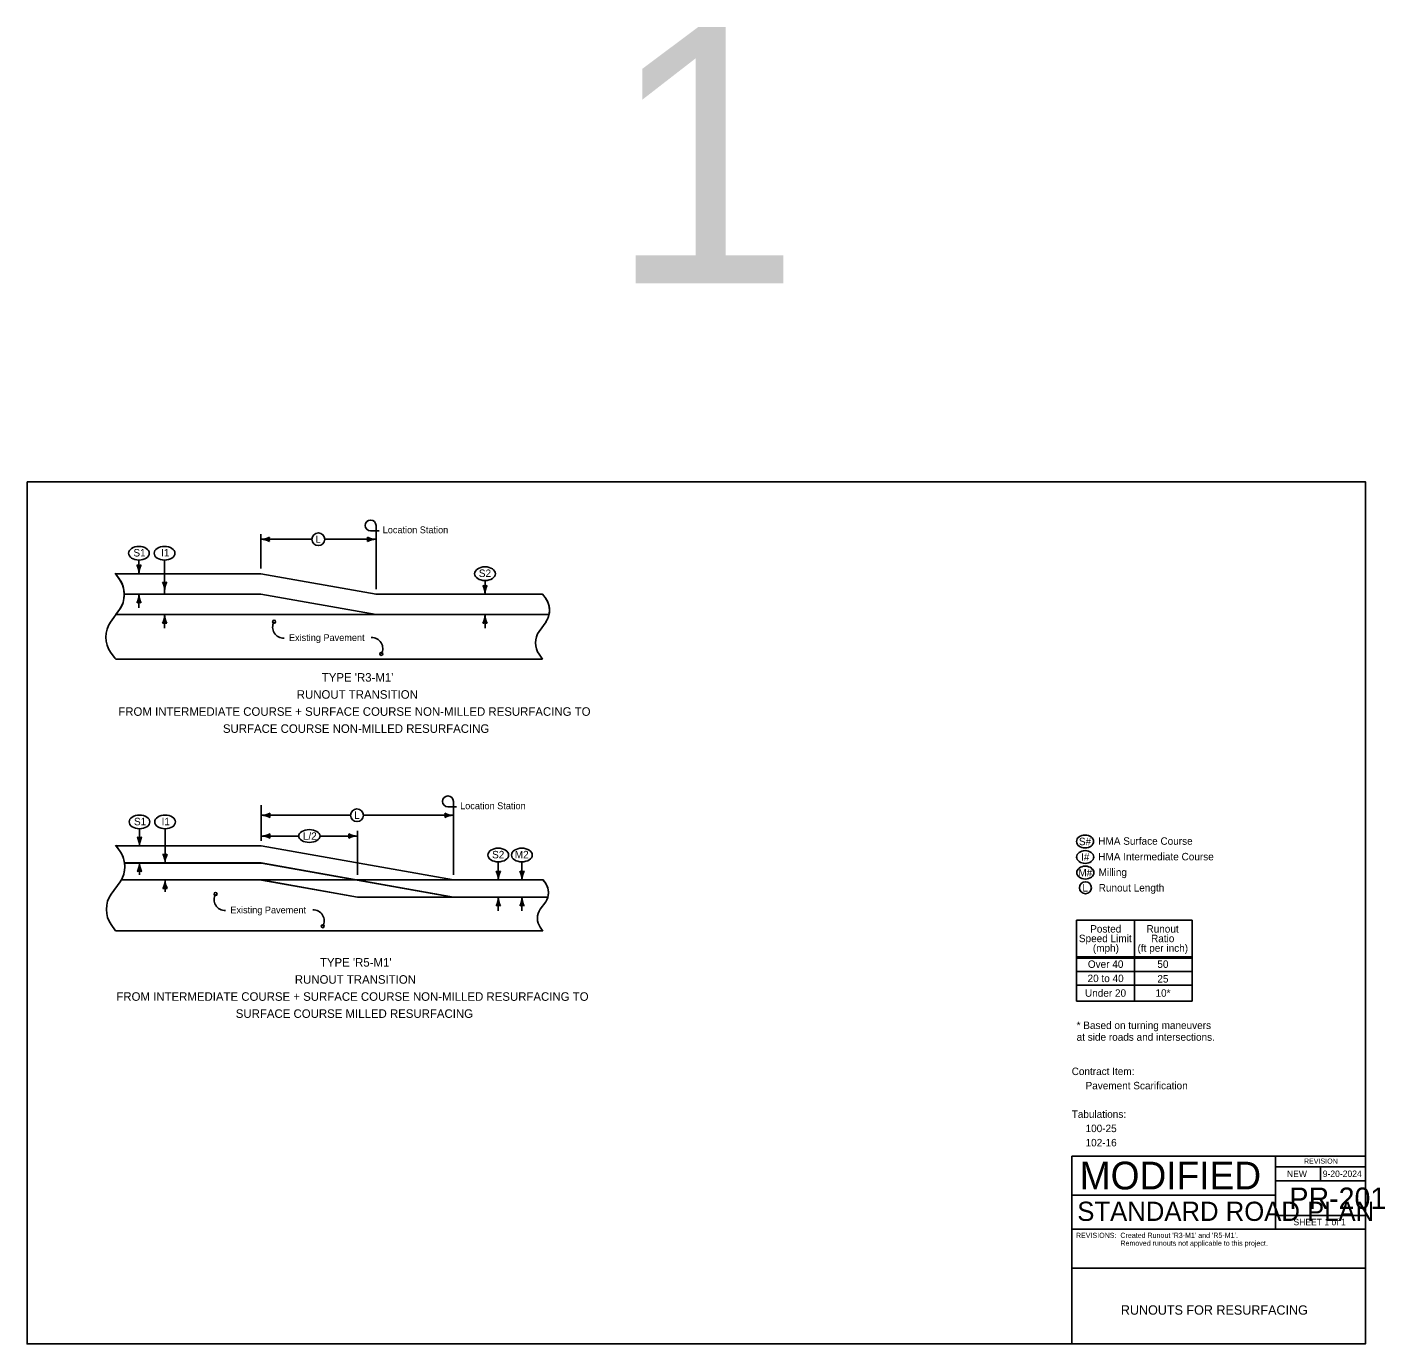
# Model space of a CAD drawing. Extents: x 10133 to 81668, y 2218 to 11018.
# Drawn here: x 10133 to 13313, y 7924 to 11009 of the extents above; entities that cross this region are included whole.
import ezdxf

# ---------------------------------------------------------------- set-up
doc = ezdxf.new("R2010")
doc.units = 0
for name, color, linetype in [('Default', 7, 'Continuous'), ('dsnNonPlotable', 7, 'Continuous'), ('dsnShtPlotShapeBatchPrint', 7, 'Continuous'), ('dsnStdBlock', 7, 'Continuous'), ('dsnStdBlockModified', 7, 'Continuous'), ('dsnStdBlockNotModified', 7, 'Continuous'), ('dsnStdBorder', 7, 'Continuous'), ('SheetBorder', 7, 'Continuous'), ('SheetText', 7, 'Continuous')]:
    doc.layers.add(name, color=color, linetype=linetype)

msp = doc.modelspace()

# ---------------------------------------------------------------- linework, layer by layer
at = {"layer": 'Default'}
for points in [[(10349.3, 9715.2), (10339.4, 9728.6), (10679.8, 9728.6), (10949.8, 9680.6), (11339.8, 9680.6), (11348, 9669.5)], [(11355.1, 9632.6), (10949.8, 9632.6), (10679.8, 9680.6), (10360, 9680.6)], [(10350.5, 9077.5), (10340.7, 9090.9), (10681.1, 9090.9), (11131.1, 9010.9), (11341.1, 9010.9), (11347.3, 9002.4)], [(11352.4, 8970.9), (11129.6, 8970.9), (10681.3, 9050.6), (10360.7, 9050.6)]]:
    msp.add_lwpolyline(points, dxfattribs=at)
for centre, major_axis, ratio, start_param in [((10323.3, 9679.9), (0, -50), 0.732645, 1.585583), ((11328.3, 9642.6), (0, -38), 0.732598, 1.304509), ((10324.6, 9042.1), (0, -50), 0.732645, 1.74011), ((11331.8, 8981.2), (0, -30), 0.73263, 1.219806)]:
    msp.add_ellipse(centre, major_axis=major_axis, ratio=ratio, start_param=start_param, end_param=2.356194, dxfattribs=at)
at = {"layer": 'dsnNonPlotable'}
for points in [[(10360, 9680.6), (10679.8, 9680.6), (10949.8, 9632.6), (10340.5, 9632.6), (10349.2, 9644.5)], [(10360.7, 9050.6), (10681.3, 9050.6), (11129.6, 8970.9), (10906.1, 8970.9), (10681.3, 9010.6), (10353.2, 9010.9)]]:
    msp.add_lwpolyline(points, dxfattribs=at)
for centre, start_param, end_param in [((10323.3, 9679.9), 0.785304, 1.585583), ((10324.6, 9042.1), 0.89539, 1.74011)]:
    msp.add_ellipse(centre, major_axis=(0, -50), ratio=0.732645, start_param=start_param, end_param=end_param, dxfattribs=at)
at = {"layer": 'dsnStdBlock'}
for p, q in [((10937.1, 9828.9), (10957.4, 9828.9)), ((10949.8, 9821.3), (10949.8, 9841.6)), ((10679.8, 9821.3), (10679.8, 9740.6)), ((10679.8, 9809.3), (10799.8, 9809.3)), ((10829.8, 9809.3), (10949.8, 9809.3)), ((10949.8, 9821.3), (10949.8, 9692.6)), ((10394.4, 9760.6), (10394.4, 9728.6)), ((10394.4, 9760.6), (10394.4, 9728.6)), ((10454.4, 9760.6), (10454.4, 9680.6)), ((10454.4, 9760.6), (10454.4, 9680.6)), ((10338.5, 9729.9), (10349.2, 9715.2)), ((10338.5, 9729.9), (10349.2, 9715.2)), ((10339.8, 9728.6), (10679.8, 9728.6)), ((10339.8, 9728.6), (10679.8, 9728.6)), ((10949.8, 9680.6), (10679.8, 9728.6)), ((11205.1, 9712.6), (11205.1, 9680.6)), ((11205.1, 9712.6), (11205.1, 9680.6)), ((10359.4, 9680.6), (10679.8, 9680.6)), ((10359.4, 9680.6), (10679.8, 9680.6)), ((10394.4, 9680.6), (10394.4, 9648.6)), ((10394.4, 9680.6), (10394.4, 9648.6)), ((10949.8, 9632.6), (10679.8, 9680.6)), ((10949.8, 9680.6), (11339.8, 9680.6)), ((10949.8, 9680.6), (11339.8, 9680.6)), ((11339.8, 9680.6), (11348, 9669.5)), ((11339.8, 9680.6), (11348, 9669.5)), ((10349.2, 9644.5), (10327.8, 9615.2)), ((10349.2, 9644.5), (10327.8, 9615.2)), ((10340.5, 9632.6), (10949.8, 9632.6)), ((10340.5, 9632.6), (10949.8, 9632.6)), ((10454.4, 9632.6), (10454.4, 9600.6)), ((10454.4, 9632.6), (10454.4, 9600.6)), ((10949.8, 9632.6), (11355.1, 9632.6)), ((10949.8, 9632.6), (11355.1, 9632.6)), ((11129.8, 9632.6), (11339.8, 9632.6)), ((11129.8, 9632.6), (11339.8, 9632.6)), ((11205.1, 9632.6), (11205.1, 9600.6)), ((11205.1, 9632.6), (11205.1, 9600.6)), ((11348, 9615.8), (11331.7, 9593.5)), ((11348, 9615.8), (11331.7, 9593.5)), ((10327.8, 9544.5), (10338.5, 9529.9)), ((10327.8, 9544.5), (10338.5, 9529.9)), ((10339.8, 9528.6), (11339.8, 9528.6)), ((10339.8, 9528.6), (11339.8, 9528.6)), ((11331.7, 9539.8), (11339.8, 9528.6)), ((11331.7, 9539.8), (11339.8, 9528.6)), ((11131.1, 9174.6), (11131.1, 9195)), ((10681.1, 9186.6), (10681.1, 9102.9)), ((10681.1, 9162.6), (10890.1, 9162.6)), ((10920.1, 9162.6), (11131.1, 9162.6)), ((11118.4, 9182.3), (11138.7, 9182.3)), ((11131.1, 9174.6), (11131.1, 9022.9)), ((10395.7, 9130.9), (10395.7, 9090.9)), ((10395.7, 9130.9), (10395.7, 9090.9)), ((10455.7, 9130.9), (10455.7, 9050.9)), ((10455.7, 9130.9), (10455.7, 9050.9)), ((10768.6, 9113.9), (10681.1, 9113.9)), ((10818.6, 9113.9), (10906.1, 9113.9)), ((10906.1, 9125.9), (10906.1, 9022.9)), ((10339.8, 9092.1), (10350.5, 9077.5)), ((10339.8, 9092.1), (10350.5, 9077.5)), ((10340.7, 9090.9), (10681.1, 9090.9)), ((10340.7, 9090.9), (10681.1, 9090.9)), ((11131.1, 9010.9), (10681.1, 9090.9)), ((10360.7, 9050.9), (10681.1, 9050.9)), ((10360.7, 9050.9), (10681.1, 9050.9)), ((10395.7, 9050.9), (10395.7, 9022.9)), ((10395.7, 9050.9), (10395.7, 9022.9)), ((11131.1, 8970.9), (10681.1, 9050.9)), ((11236.1, 9053.4), (11236.1, 9010.9)), ((11236.1, 9053.4), (11236.1, 9010.9)), ((11291.5, 9053.4), (11291.5, 9010.9)), ((11291.5, 9053.4), (11291.5, 9010.9)), ((10350.5, 9006.8), (10329.1, 8977.5)), ((10350.5, 9006.8), (10329.1, 8977.5)), ((10353.2, 9010.9), (10681.1, 9010.9)), ((10353.2, 9010.9), (10681.1, 9010.9)), ((10455.7, 9010.9), (10455.7, 8982.9)), ((10455.7, 9010.9), (10455.7, 8982.9)), ((10681.1, 9010.9), (11131.1, 9010.9)), ((10681.1, 9010.9), (11131.1, 9010.9)), ((10906.1, 8970.9), (10681.1, 9010.9)), ((11131.1, 9010.9), (11341.1, 9010.9)), ((11131.1, 9010.9), (11341.1, 9010.9)), ((11340.9, 9011.2), (11347.3, 9002.4)), ((11340.9, 9011.2), (11347.3, 9002.4)), ((10906.1, 8970.9), (11352.4, 8970.9)), ((10906.1, 8970.9), (11352.4, 8970.9)), ((11236.1, 8970.9), (11236.1, 8938.9)), ((11291.5, 8970.9), (11291.5, 8938.9)), ((11291.5, 8970.9), (11291.5, 8938.9)), ((11347.3, 8960), (11334.4, 8942.4)), ((11347.3, 8960), (11334.4, 8942.4)), ((10329.1, 8906.8), (10339.8, 8892.1)), ((10329.1, 8906.8), (10339.8, 8892.1)), ((12591.1, 8917.1), (12591.1, 8726.9)), ((12591.1, 8917.1), (12861.4, 8917.1)), ((12726.3, 8917.1), (12726.3, 8726.9)), ((12861.4, 8917.1), (12861.4, 8726.9)), ((10339.8, 8892.1), (11340.2, 8892.1)), ((10339.8, 8892.1), (11340.2, 8892.1)), ((11334.4, 8900), (11340.9, 8891.2)), ((11334.4, 8900), (11340.9, 8891.2)), ((12591.1, 8830.8), (12861.4, 8830.8)), ((12591.1, 8827.8), (12861.4, 8827.8)), ((12591.1, 8796.6), (12861.4, 8796.6)), ((12591.1, 8764.2), (12861.4, 8764.2)), ((12591.1, 8726.9), (12861.4, 8726.9))]:
    msp.add_line(p, q, dxfattribs=at)
msp.add_lwpolyline([(11352.4, 8970.9), (10906.1, 8970.9), (10681.1, 9010.9), (11341.1, 9010.9), (11347.3, 9002.4), (11347.3, 9002.4)], dxfattribs=at)
for centre, radius in [((10814.8, 9809.3), 15), ((10711.1, 9616), 3.56), ((10962.2, 9540.6), 3.56), ((10905.1, 9162.6), 15), ((12611.8, 8992.7), 14), ((10573.9, 8977.9), 3.56), ((10825, 8902.5), 3.56)]:
    msp.add_circle(centre, radius, dxfattribs=at)
for centre, radius, start, end in [((10937.1, 9841.6), 12.7, 0, 270), ((10679.8, 9852.5), 43.2, 270, 298.0725), ((10679.8, 9766.1), 43.2, 61.9275, 90), ((10716, 9809.3), 16.7, 162.2666, 197.7334), ((10913.6, 9809.3), 16.7, 342.2666, 17.7333), ((10949.8, 9852.5), 43.2, 241.9275, 270), ((10949.8, 9766.1), 43.2, 90, 118.0725), ((10394.4, 9764.8), 16.7, 252.2666, 287.7333), ((10351.3, 9728.6), 43.2, 360, 28.0725), ((10394.4, 9764.8), 16.7, 252.2666, 287.7333), ((10351.3, 9728.6), 43.2, 360, 28.0725), ((10437.6, 9728.6), 43.2, 151.9275, 180), ((10437.6, 9728.6), 43.2, 151.9275, 180), ((10454.4, 9724.8), 16.7, 252.2666, 287.7333), ((10411.3, 9688.6), 43.2, 360, 28.0725), ((10454.4, 9724.8), 16.7, 252.2666, 287.7333), ((10411.3, 9688.6), 43.2, 360, 28.0725), ((10497.6, 9688.6), 43.2, 151.9275, 180), ((10497.6, 9688.6), 43.2, 151.9275, 180), ((11205.1, 9716.8), 16.7, 252.2666, 287.7333), ((11161.9, 9680.6), 43.2, 360, 28.0725), ((11205.1, 9716.8), 16.7, 252.2666, 287.7333), ((11161.9, 9680.6), 43.2, 360, 28.0725), ((11248.3, 9680.6), 43.2, 151.9275, 180), ((11248.3, 9680.6), 43.2, 151.9275, 180), ((10351.3, 9680.6), 43.2, 331.9275, 360), ((10351.3, 9680.6), 43.2, 331.9275, 360), ((10437.6, 9680.6), 43.2, 180, 208.0725), ((10437.6, 9680.6), 43.2, 180, 208.0725), ((10394.4, 9644.4), 16.7, 72.2666, 107.7334), ((10394.4, 9644.4), 16.7, 72.2666, 107.7334), ((10411.3, 9632.6), 43.2, 331.9275, 360), ((10411.3, 9632.6), 43.2, 331.9275, 360), ((10454.4, 9596.4), 16.7, 72.2666, 107.7334), ((10454.4, 9596.4), 16.7, 72.2666, 107.7334), ((10497.6, 9632.6), 43.2, 180, 208.0725), ((10497.6, 9632.6), 43.2, 180, 208.0725), ((10733.2, 9603.2), 25.6, 150.0683, 272.8436), ((11161.9, 9632.6), 43.2, 331.9275, 360), ((11161.9, 9632.6), 43.2, 331.9275, 360), ((11205.1, 9596.4), 16.7, 72.2666, 107.7334), ((11205.1, 9596.4), 16.7, 72.2666, 107.7334), ((11248.3, 9632.6), 43.2, 180, 208.0725), ((11248.3, 9632.6), 43.2, 180, 208.0725), ((10940, 9553.4), 25.6, 330.0683, 92.8436), ((11118.4, 9195), 12.7, 0, 270), ((10681.1, 9205.8), 43.2, 270, 298.0725), ((10681.1, 9119.5), 43.2, 61.9275, 90), ((10717.3, 9162.6), 16.7, 162.2666, 197.7334), ((11094.9, 9162.6), 16.7, 342.2666, 17.7333), ((11131.1, 9205.8), 43.2, 241.9275, 270), ((11131.1, 9119.5), 43.2, 90, 118.0725), ((10395.7, 9127.1), 16.7, 252.2666, 287.7333), ((10352.6, 9090.9), 43.2, 360, 28.0725), ((10395.7, 9127.1), 16.7, 252.2666, 287.7333), ((10352.6, 9090.9), 43.2, 360, 28.0725), ((10438.9, 9090.9), 43.2, 151.9275, 180), ((10438.9, 9090.9), 43.2, 151.9275, 180), ((10681.1, 9157), 43.2, 270, 298.0725), ((10681.1, 9070.7), 43.2, 61.9275, 90), ((10717.3, 9113.9), 16.7, 162.2666, 197.7334), ((10869.9, 9113.9), 16.7, 342.2666, 17.7333), ((10906.1, 9157), 43.2, 241.9275, 270), ((10906.1, 9070.7), 43.2, 90, 118.0725), ((10455.7, 9087.1), 16.7, 252.2666, 287.7333), ((10412.6, 9050.9), 43.2, 360, 28.0725), ((10455.7, 9087.1), 16.7, 252.2666, 287.7333), ((10412.6, 9050.9), 43.2, 360, 28.0725), ((10498.9, 9050.9), 43.2, 151.9275, 180), ((10498.9, 9050.9), 43.2, 151.9275, 180), ((10352.6, 9050.9), 43.2, 331.9275, 360), ((10352.6, 9050.9), 43.2, 331.9275, 360), ((10438.9, 9050.9), 43.2, 180, 208.0725), ((10438.9, 9050.9), 43.2, 180, 208.0725), ((10395.7, 9014.7), 16.7, 72.2666, 107.7334), ((10395.7, 9014.7), 16.7, 72.2666, 107.7334), ((10412.6, 9010.9), 43.2, 331.9275, 360), ((10412.6, 9010.9), 43.2, 331.9275, 360), ((10498.9, 9010.9), 43.2, 180, 208.0725), ((10498.9, 9010.9), 43.2, 180, 208.0725), ((11236.1, 9047.1), 16.7, 252.2666, 287.7333), ((11192.9, 9010.9), 43.2, 360, 28.0725), ((11236.1, 9047.1), 16.7, 252.2666, 287.7333), ((11192.9, 9010.9), 43.2, 360, 28.0725), ((11279.3, 9010.9), 43.2, 151.9275, 180), ((11279.3, 9010.9), 43.2, 151.9275, 180), ((11291.5, 9047.1), 16.7, 252.2666, 287.7333), ((11248.4, 9010.9), 43.2, 360, 28.0725), ((11291.5, 9047.1), 16.7, 252.2666, 287.7333), ((11248.4, 9010.9), 43.2, 360, 28.0725), ((11334.7, 9010.9), 43.2, 151.9275, 180), ((11334.7, 9010.9), 43.2, 151.9275, 180), ((10455.7, 8974.7), 16.7, 72.2666, 107.7334), ((10455.7, 8974.7), 16.7, 72.2666, 107.7334), ((10596, 8965.1), 25.6, 150.0683, 272.8436), ((11192.9, 8970.9), 43.2, 331.9275, 360), ((11192.9, 8970.9), 43.2, 331.9275, 360), ((11279.3, 8970.9), 43.2, 180, 208.0725), ((11279.3, 8970.9), 43.2, 180, 208.0725), ((11248.4, 8970.9), 43.2, 331.9275, 360), ((11248.4, 8970.9), 43.2, 331.9275, 360), ((11334.7, 8970.9), 43.2, 180, 208.0725), ((11334.7, 8970.9), 43.2, 180, 208.0725), ((10802.9, 8915.3), 25.6, 330.0683, 92.8436), ((11236.1, 8934.7), 16.7, 72.2666, 107.7334), ((11236.1, 8934.7), 16.7, 72.2666, 107.7334), ((11291.5, 8934.7), 16.7, 72.2666, 107.7334), ((11291.5, 8934.7), 16.7, 72.2666, 107.7334)]:
    msp.add_arc(centre, radius, start, end, dxfattribs=at)
for centre, major_axis, ratio in [((10394.4, 9776.6), (24.3, 0), 0.658717), ((10454.4, 9776.6), (24.3, 0), 0.658717), ((11205.1, 9728.6), (24.3, 0), 0.658717), ((10395.7, 9146.9), (24.3, 0), 0.658717), ((10455.7, 9146.9), (24.3, 0), 0.658717), ((10793.6, 9113.9), (25, 0), 0.6), ((12610.8, 9101.1), (-20, 0), 0.749963), ((11236.1, 9069.4), (24.3, 0), 0.658717), ((11291.5, 9069.4), (-24.3, 0), 0.658717), ((12611.1, 9064.7), (-20, 0), 0.749963), ((12611.4, 9028.2), (-20, 0), 0.749963)]:
    msp.add_ellipse(centre, major_axis=major_axis, ratio=ratio, dxfattribs=at)
for centre, major_axis, ratio, start_param in [((10323.3, 9679.9), (0, -50), 0.732645, 0.785398), ((10323.3, 9679.9), (0, -50), 0.732645, 0.785398), ((11328.3, 9642.6), (0, -38), 0.732598, 0.785398), ((11328.3, 9642.6), (0, -38), 0.732598, 0.785398), ((10353.7, 9579.9), (0, 50), 0.732645, 0.785398), ((10353.7, 9579.9), (0, 50), 0.732645, 0.785398), ((11351.3, 9566.6), (0, 38), 0.732598, 0.785398), ((11351.3, 9566.6), (0, 38), 0.732598, 0.785398), ((10324.6, 9042.1), (0, -50), 0.732645, 0.785398), ((10324.6, 9042.1), (0, -50), 0.732645, 0.785398), ((11331.8, 8981.2), (0, -30), 0.73263, 0.785398), ((11331.8, 8981.2), (0, -30), 0.73263, 0.785398), ((11331.8, 8981.2), (0, -30), 0.73263, 1.219806), ((10355, 8942.1), (0, 50), 0.732645, 0.785398), ((10355, 8942.1), (0, 50), 0.732645, 0.785398), ((11350, 8921.2), (0, 30), 0.73263, 0.785398), ((11350, 8921.2), (0, 30), 0.73263, 0.785398)]:
    msp.add_ellipse(centre, major_axis=major_axis, ratio=ratio, start_param=start_param, end_param=2.356194, dxfattribs=at)
at = {"layer": 'dsnStdBlockModified'}
for p, q in [((13056.6, 8364), (13056.6, 8272.7)), ((13056.6, 8339.1), (13267.5, 8339.1)), ((13162.1, 8339.1), (13162.1, 8305.9)), ((13056.6, 8305.9), (13267.5, 8305.9)), ((13056.6, 8272.7), (13056.6, 8192.7)), ((13267.5, 8224.9), (13056.6, 8224.9)), ((12579.5, 8192.7), (13267.5, 8192.7))]:
    msp.add_line(p, q, dxfattribs=at)
msp.add_lwpolyline([(12579.5, 8364), (13267.5, 8364), (13267.5, 7924), (12579.5, 7924)], close=True, dxfattribs=at)
at = {"layer": 'dsnStdBorder'}
for p, q in [((12579.5, 8272.7), (13056.6, 8272.7)), ((12579.5, 8101.7), (13267.5, 8101.7))]:
    msp.add_line(p, q, dxfattribs=at)
at = {"layer": 'SheetBorder'}
msp.add_lwpolyline([(10132.5, 9944), (13267.5, 9944), (13267.5, 7924), (10132.5, 7924)], close=True, dxfattribs=at)

# ---------------------------------------------------------------- texts
at = {"layer": 'dsnShtPlotShapeBatchPrint'}
msp.add_text('L/2', height=17.5, dxfattribs=at).set_placement((10778.4, 9105.1))
at = {"layer": 'dsnStdBlock'}
for s, p in [('Contract Item:', (12579.5, 8553.8)), ('     Pavement Scarification', (12579.5, 8520.4)), ('Tabulations:', (12579.5, 8453.5)), ('     100-25', (12579.5, 8420.1)), ('     102-16', (12579.5, 8386.7))]:
    msp.add_text(s, height=17.5, dxfattribs=at).set_placement(p)
at = {"layer": 'dsnStdBlockModified'}
for s, height, p in [('MODIFIED', 65, (12598.3, 8285.9)), ('REVISION', 12, (13123.6, 8346.2)), ('NEW', 15, (13083.8, 8314.7)), ('9-20-2024', 15, (13167.6, 8315.1)), ('PR-201', 50, (13089.7, 8240.2)), ('STANDARD ROAD PLAN', 45.001, (12592.6, 8212.1)), ('SHEET 1 of 1', 15, (13099, 8202)), ('RUNOUTS FOR RESURFACING', 22, (12694.7, 7992.3))]:
    msp.add_text(s, height=height, dxfattribs=at).set_placement(p)
at = {"layer": 'dsnStdBlockNotModified'}
for s, height, p in [('Location Station', 16, (10965.5, 9823.4)), ('L', 16, (10808.2, 9801.3)), ('S1', 17.5, (10381.5, 9768.9)), ('I1', 17.5, (10446.2, 9768.9)), ('S2', 17.5, (11190.7, 9720.9)), ('Existing Pavement', 16, (10745.8, 9570.8)), ("TYPE 'R3-M1'", 20, (10822.8, 9475.6)), ('RUNOUT TRANSITION', 20, (10764.1, 9435.6)), ('FROM INTERMEDIATE COURSE + SURFACE COURSE NON-MILLED RESURFACING TO', 20, (10346, 9395.6)), ('SURFACE COURSE NON-MILLED RESURFACING', 20, (10591.1, 9355.6)), ('Location Station', 16, (11146.8, 9176.8)), ('L', 17.5, (10898.8, 9153.9)), ('S1', 17.5, (10382.8, 9139.1)), ('I1', 17.5, (10447.5, 9139.1)), ('S#', 17.5, (12596.4, 9092.4)), ('HMA Surface Course', 17.5, (12641.8, 9093.4)), ('S2', 17.5, (11221.7, 9061.6)), ('M2', 17.5, (11274.9, 9061.6)), ('I#', 17.5, (12601.4, 9055.9)), ('HMA Intermediate Course', 17.5, (12641.8, 9056.9)), ('M#', 17.5, (12595.1, 9019.4)), ('Milling', 17.5, (12642.6, 9020.4)), ('L', 17.5, (12604.5, 8983.9)), ('Runout Length', 17.5, (12642.8, 8983.9)), ('Existing Pavement', 16, (10608.6, 8932.7)), ('Posted', 17.5, (12622.8, 8887.7)), ('Speed Limit', 17.5, (12596.4, 8865.2)), ('Runout', 17.5, (12754.6, 8887.7)), ('Ratio', 17.5, (12765.4, 8865.2)), ('(mph)', 17.5, (12629.1, 8842.7)), ('(ft per inch)', 17.5, (12733.8, 8842.7)), ("TYPE 'R5-M1'", 20, (10818.4, 8807.8)), ('Over 40', 17.5, (12617.4, 8805)), ('50', 17.5, (12780.2, 8805)), ('RUNOUT TRANSITION', 20, (10759.6, 8767.8)), ('20 to 40', 17.5, (12616.7, 8771.6)), ('25', 17.5, (12780.2, 8770.6)), ('FROM INTERMEDIATE COURSE + SURFACE COURSE NON-MILLED RESURFACING TO', 20, (10341.5, 8727.8)), ('Under 20', 17.5, (12610.7, 8737.3)), ('10*', 17.5, (12775.8, 8737.3)), ('SURFACE COURSE MILLED RESURFACING', 20, (10621.3, 8687.8)), ('* Based on turning maneuvers ', 17.5, (12591.1, 8661.7)), ('at side roads and intersections.', 17.5, (12591.1, 8634.2))]:
    msp.add_text(s, height=height, dxfattribs=at).set_placement(p)
at = {"layer": 'dsnStdBorder'}
for s, p in [('REVISIONS:', (12589.5, 8172.3)), ("Created Runout 'R3-M1' and 'R5-M1'.", (12693.6, 8172.4)), ('Removed runouts not applicable to this project.', (12693.6, 8153.9))]:
    msp.add_text(s, height=12, dxfattribs=at).set_placement(p)
at = {"layer": 'SheetText'}
msp.add_text('1', height=600, dxfattribs=at).set_placement((11496.6, 10409.2))

doc.saveas('drawing.dxf')
